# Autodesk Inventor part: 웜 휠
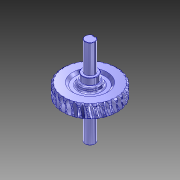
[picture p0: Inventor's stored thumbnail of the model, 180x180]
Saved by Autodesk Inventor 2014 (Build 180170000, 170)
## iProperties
Created: 2013-01
Part Number: 웜 휠
Material: 탄소강
Document SubType Name: Modeling
Designer: 한국산업디자인학원[gmhk.co.kr]
Categories: <?xml version="1.0" encoding="UTF-16"?> <MemberInstance><Categories><FamilyTemplate><FamilyTemplateParameter ValueType="xs:double" Id="1" ObjectReferenceKey="da
Density: 7.87 g/cm^3
Mass: 6989.44 g
Surface Area: 1041.74 cm^2
Volume: 888.112 cm^3
Appearance: _시험-파란색 크롬
CustomPartVersion: 1
Author: 한국산업디자인학원[gmhk.co.kr]
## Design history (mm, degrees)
body "Solid1"
node "톱니 평면"
sketch "기본 본체 스케치"
  geometry: L1 (0, -14)-(0, 14) reference; L2 (0, 20)-(77.639, 20); L3 (77.639, 20)-(82.5, 15.652); L4 (-10, 0)-(60, 0) reference; L5 (82.5, 15.652)-(82.5, -15.652); L6 (0, -20)-(77.639, -20); L7 (0, 20)-(0, -20); L8 (77.639, -20)-(82.5, -15.652); C1 r 20 at (100, 0)
  constraints: 14 end point, 3 symmetric about line, 2 perpendicular, 2 point on line, 1 centre point, 1 collinear
  dimensions: "d50" = 41.8103 deg angle of L3 L2 (= da_fi); "d87" = 165 diameter of L5 L1 (= da_dae); "d89" = 40 diameter of C1 (= 2 x da_aw - da_da); "d92" = 40 distance of L2.start L6.start (= da_b); "d93" = 100 distance from line of C1.centre L7 (= da_aw)
revolve "기본 본체" stored, may be unused: angle "d35" = 90 deg
revolve "기본 본체2" stored, may be unused: angle "d90" = 90 deg
workplane "Work Plane13"
revolve "톱니" stored, may be unused: angle "d43" = 90 deg
pattern_circular "톱니 패턴" dims angle "d46" = 360 deg
workplane "Work Plane14"
workplane "Work Plane15"
revolve "회전6" stored, may be unused: angle "d97" = 90 deg
revolve "회전7" stored, may be unused: angle "d104" = 90 deg
fillet "모깎기1" dims "d105" = 5
chamfer "모따기1" distance "d106" = 1; stored, may be unused: second distance "d107" = 2, angle "d108" = 45 deg
node "작업 평면16"
sketch "스케치11"
  geometry: L1 (-14, 43)-(14, 43) reference; L2 (4, 43)-(4, 22); L3 (-4, 22)-(-4, 43); A1 r 4 centre (0, 22) between (-4, 22) and (4, 22); 2 further points
  constraints: 4 end point, 2 perpendicular, 2 point on circle, 2 point on line, 2 tangent, 1 centre point, 1 midpoint, 1 vertical alignment
  dimensions: "d109" = 8 distance between parallel lines of L2 L3; "d110" = 25 dimension on A1 L1
extrude "돌출1" cut sketch "스케치11" distance "d111" = 4; taper "d112" = 0 deg
mirror "대칭1"
sketch "톱니 스케치"
  geometry: L1 (10, 5.301)-(10, -5.301) reference; L2 (-32.842, 0)-(-12.948, 0) reference; L3 (-90, 6.896)-(-90, -6.896); L4 (-90, -6.896)-(-71, -6.896); L5 (-71, -6.896)-(-59, -2.529); L6 (-59, -2.529)-(-59, 0); L7 (-59, 2.529)-(-71, 6.896); L8 (-71, 6.896)-(-90, 6.896); L9 (-59, 2.529)-(-59, 0); L10 (-65, 0)-(-65, -4.712)
  constraints: 16 end point, 4 perpendicular, 3 equal length, 2 point on line, 1 midpoint, 1 parallel, 1 vertical
  dimensions: "d38" = 100 distance between parallel lines of L1 L3 (= da_aw); "d39" = 20 deg angle of L7 L8 (= da_alfat); "d40" = 19 distance of L7.end L3.start (= 0.5 x da_df1); "d41" = 25 distance between parallel lines of L3 L10 (= 0.5 x da_d1); "d42" = 4.71239 distance of L10.start L10.end (= 0.3 x da_px)
sketch "Sketch8"
  geometry: C1 r 77.639 at (0, 0) reference; C2 r 75 at (0, 0)
  constraints: 1 centre point, 1 coincident
  dimensions: "d77" = 150 diameter of C2 (= da_dw)
body "Srf1"
sketch "스케치9"
  geometry: L1 (-74.283, 20)-(-74.054, 20) reference; L2 (-74.054, 20)-(-74.261, 20) reference; L3 (-74.261, 20)-(-75.727, 20) reference; L4 (-77.355, 20)-(-75.727, 20) reference; L5 (-77.355, 20)-(-77.106, 20) reference; L6 (-77.106, 20)-(-76.222, 20) reference; L7 (-76.222, 20)-(-77.633, 20) reference; L8 (-77.045, 20)-(-77.633, 20) reference; L9 (-77.045, 20)-(-76.789, 20) reference; L10 (-76.789, 20)-(-74.852, 20) reference; L11 (-74.852, 20)-(-76.145, 20) reference; L12 (-73.369, 20)-(-76.145, 20) reference; L13 (-73.369, 20)-(-73.116, 20) reference; L14 (-73.116, 20)-(-70.211, 20) reference; L15 (-70.211, 20)-(-71.33, 20) reference; L16 (-66.486, 20)-(-71.33, 20) reference; L17 (-66.486, 20)-(-66.247, 20) reference; L18 (-66.247, 20)-(-62.501, 20) reference; L19 (-62.501, 20)-(-63.397, 20) reference; L20 (-56.697, 20)-(-63.397, 20) reference; L21 (-56.697, 20)-(-56.483, 20) reference; L22 (-56.483, 20)-(-52.059, 20) reference; L23 (-52.059, 20)-(-52.693, 20) reference; L24 (-44.431, 20)-(-52.693, 20) reference; L25 (-44.431, 20)-(-44.25, 20) reference; L26 (-44.25, 20)-(-39.342, 20) reference; L27 (-39.342, 20)-(-39.687, 20) reference; L28 (-30.222, 20)-(-39.687, 20) reference; L29 (-30.222, 20)-(-30.084, 20) reference; L30 (-30.084, 20)-(-24.906, 20) reference; L31 (-24.906, 20)-(-24.945, 20) reference; L32 (-14.693, 20)-(-24.945, 20) reference; L33 (-14.693, 20)-(-14.602, 20) reference; L34 (-14.602, 20)-(-9.381, 20) reference; L35 (-9.381, 20)-(-9.114, 20) reference; L36 (1.479, 20)-(-9.114, 20) reference; L37 (1.479, 20)-(1.517, 20) reference; L38 (1.517, 20)-(6.554, 20) reference; L39 (6.554, 20)-(7.116, 20) reference; L40 (17.586, 20)-(7.116, 20) reference; L41 (17.586, 20)-(17.571, 20) reference; L42 (17.571, 20)-(22.202, 20) reference; L43 (22.202, 20)-(23.034, 20) reference; L44 (32.924, 20)-(23.034, 20) reference; L45 (32.924, 20)-(32.856, 20) reference; L46 (32.856, 20)-(36.88, 20) reference; L47 (36.88, 20)-(37.946, 20) reference; L48 (46.823, 20)-(37.946, 20) reference; L49 (46.823, 20)-(46.705, 20) reference; L50 (46.705, 20)-(49.946, 20) reference; L51 (49.946, 20)-(51.2, 20) reference; L52 (58.676, 20)-(51.2, 20) reference; L53 (58.676, 20)-(58.514, 20) reference; L54 (58.514, 20)-(60.83, 20) reference; L55 (60.83, 20)-(62.216, 20) reference; L56 (67.965, 20)-(62.216, 20) reference; L57 (67.965, 20)-(67.764, 20) reference; L58 (67.764, 20)-(69.055, 20) reference; L59 (69.055, 20)-(70.512, 20) reference; L60 (74.283, 20)-(70.512, 20) reference; L61 (74.283, 20)-(74.054, 20) reference; L62 (74.054, 20)-(74.261, 20) reference; L63 (74.261, 20)-(75.727, 20) reference; L64 (77.355, 20)-(75.727, 20) reference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
  constraints: 8 end point, 3 point on line, 2 perpendicular, 1 parallel
  dimensions: "d94" = 90 diameter of L122.end L121; "d95" = 135 deg angle of L123 L122; "d96" = 13 distance from line of L121.start L122
node "투영된 루프1"
sketch "스케치10"
  geometry: L1 (45, 13)-(-45, 13) reference; L2 (0, 13)-(0, 133); L3 (0, 133)-(-15, 133); L4 (-15, 133)-(-15, 47); L5 (-15, 47)-(-22.5, 47); L6 (-22.5, 47)-(-22.5, 28); L7 (-22.5, 28)-(-30, 28); L8 (-30, 28)-(-30, 13); L9 (30, 47)-(-30, 47) reference; 1 further point
  constraints: 14 end point, 4 parallel, 3 perpendicular, 1 collinear, 1 midpoint, 1 point on line
  dimensions: "d99" = 30 diameter of L4 L2; "d100" = 45 diameter of L6 L2; "d101" = 60 diameter of L8 L2; "d102" = 15 distance between parallel lines of L7 L1; "d103" = 120 distance of L2.start L2.end
node "참조1"
feature "피치 지름" dims "d78" = 40 (= da_b), "d79" = 0
other parameters: "da_aw" = 100 [user parameter; used in 5 equation terms], "da_fi" = 41.8103 deg [user parameter; used in 1 equation term], "da_b" = 40 [user parameter; used in 2 equation terms], "da_df" = 138 [user parameter], "da_beta" = 1.97396 [user parameter; used in 1 equation term], "da_alfat" = 20 deg [user parameter; used in 1 equation term], "da_df1" = 38 [user parameter; used in 1 equation term], "da_px" = 90 deg [user parameter; used in 1 equation term], "d37" = -1.97396 (computed from da_rightdir, da_beta), "d69" = 0, "d73" = 0, "d75" = 6 deg (computed from da_z), "da_dw" = 150 [user parameter; used in 1 equation term], "da_rightdir" = 0 [user parameter; used in 1 equation term], "d80" = 0, "d81" = 0, "d82" = 0, "d83" = 6 deg (computed from da_z), "d84" = 0, "d85" = 180 deg, "da_dae" = 165 [user parameter; used in 1 equation term]
